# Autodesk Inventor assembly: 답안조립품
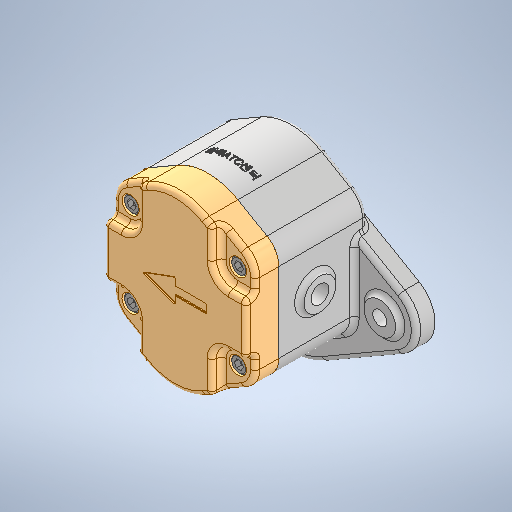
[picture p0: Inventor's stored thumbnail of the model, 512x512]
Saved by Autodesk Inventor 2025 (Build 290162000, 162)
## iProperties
Created: 2026-09
Part Number: 답안조립품
Document SubType Name: Assembly
Designer: KDI
Mass: 2259.55 g
Surface Area: 1235.53 cm^2
Volume: 698.337 cm^3
Density: 3.23562 g/cm^3
Author: KDI
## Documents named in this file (11)
- C:\Users\KDI\Desktop\660903V1004\답안조립품.iam
- C:\Users\KDI\Desktop\660903V1004\본체\본체.ipt
- C:\Users\KDI\Desktop\660903V1004\DU 부시\DU 부시.ipt
- C:\Users\KDI\Desktop\660903V1004\스퍼기어\스퍼기어.ipt
- C:\Users\KDI\Desktop\660903V1004\구동기어\구동기어.ipt
- C:\Users\KDI\Desktop\660903V1004\오일 실 16 30 7\오일 실 16 30 7.ipt
- C:\Users\KDI\Desktop\660903V1004\가이드 블록\가이드 블록.ipt
- C:\Users\KDI\Desktop\660903V1004\3자 실링\3자 실링.ipt
- C:\Users\KDI\Desktop\660903V1004\커버\커버.ipt
- C:\Users\KDI\Desktop\660903V1004\실링\실링.ipt
- C:\Users\KDI\Desktop\660903V1004\6각 구멍붙이 볼트 M6x16\6각 구멍붙이 볼트 M6x16.ipt
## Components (11 placed, 5 different names)
1. DU 부시:1
2. DU 부시:2
3. DU 부시:3
4. DU 부시:4
5. 구동기어:1
6. 가이드 블록:1
7. 3자 실링:1
8. 6각 구멍붙이 볼트 M6x16:3
9. 6각 구멍붙이 볼트 M6x16:4
10. 6각 구멍붙이 볼트 M6x16:5
11. 6각 구멍붙이 볼트 M6x16:6
